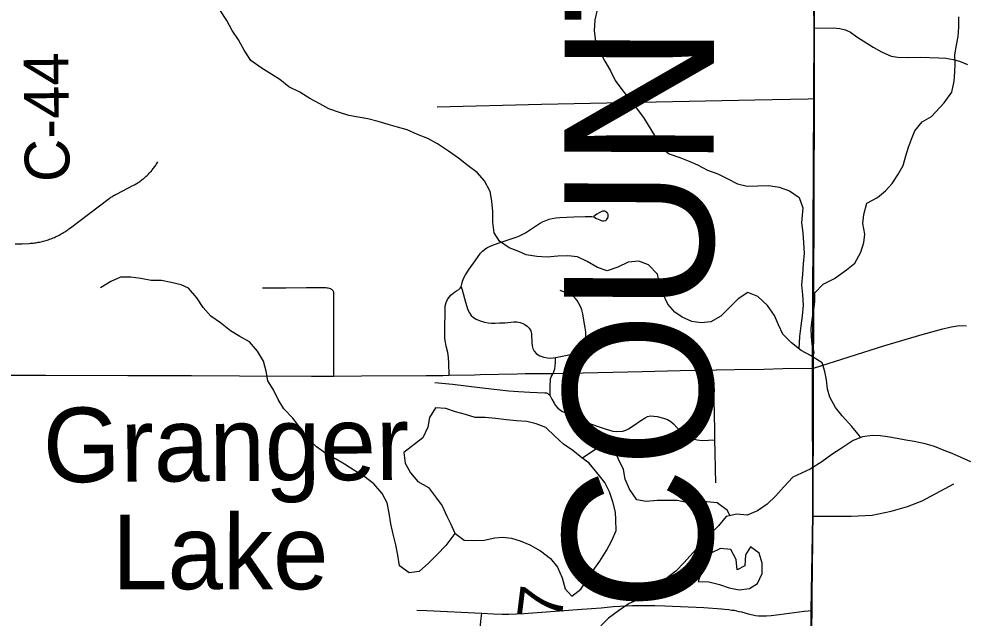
# Model space of a CAD drawing. Extents: x 0 to 34, y 0 to 22.
# Drawn here: x 6.974 to 8.175, y 15.589 to 16.35 of the extents above; entities that cross this region are included whole.
import ezdxf

# ---------------------------------------------------------------- set-up
doc = ezdxf.new("R2010")
doc.units = 0
for name, color, linetype in [('GM_X_Corporation', 7, 'Continuous'), ('GM_X_County_Road', 7, 'Continuous'), ('GM_X_County_Road_Text', 7, 'Continuous'), ('GM_X_County_Text', 7, 'Continuous'), ('GM_X_Minor_Lake', 7, 'Continuous'), ('GM_X_Minor_Lake_Text', 7, 'Continuous'), ('GM_X_Minor_River', 7, 'Continuous'), ('GM_X_Township_Road', 7, 'Continuous'), ('GM_X_Township_Road_Text', 7, 'Continuous')]:
    doc.layers.add(name, color=color, linetype=linetype)

msp = doc.modelspace()

# ---------------------------------------------------------------- linework, layer by layer
at = {"layer": 'GM_X_Corporation'}
for points in [[(2.1, 20.9), (2.1, 14.1), (7.9734, 14.1), (7.9726, 14.5453), (7.9765, 15.2637), (7.9792, 15.5481), (7.979, 15.5988), (7.9808, 15.7192), (7.9807, 15.9078), (7.9821, 16.2487), (7.9825, 16.3395), (7.9818, 16.3982), (7.9825, 16.6077), (7.9838, 16.7968), (7.9877, 17.3871), (7.9891, 17.5498), (7.991, 17.7727), (7.9901, 18.1613)], [(7.9901, 18.1613), (7.991, 17.7727), (7.9891, 17.5498), (7.9877, 17.3871), (7.9838, 16.7968), (7.9825, 16.6077), (7.9818, 16.3982), (7.9825, 16.3395), (7.9821, 16.2487), (7.9807, 15.9078), (7.9808, 15.7192), (7.979, 15.5988), (7.9792, 15.5481), (7.9765, 15.2637), (7.9726, 14.5453), (7.9734, 14.1), (8.9, 14.1), (8.9, 20.9)], [(7.9901, 18.1613), (7.991, 17.7727), (7.9891, 17.5498), (7.9877, 17.3871), (7.9838, 16.7968), (7.9825, 16.6077), (7.9818, 16.3982), (7.9825, 16.3395), (7.9821, 16.2487), (7.9807, 15.9078), (7.9808, 15.7192), (7.979, 15.5988), (7.9792, 15.5481), (7.9765, 15.2637), (7.9726, 14.5453), (8.3169, 14.5418), (8.5518, 14.5426), (8.5844, 14.5431), (8.8409, 14.5545), (8.9, 14.5547), (8.9, 19.1229)], [(7.9901, 18.1613), (7.991, 17.7727), (7.9891, 17.5498), (7.9877, 17.3871), (7.9838, 16.7968), (7.9825, 16.6077), (7.9818, 16.3982), (7.9825, 16.3395), (7.9821, 16.2487), (7.9807, 15.9078), (7.9808, 15.7192), (7.979, 15.5988), (7.9792, 15.5481), (7.9765, 15.2637), (7.9726, 14.5453), (7.0871, 14.5429), (7.0197, 14.5427), (6.4941, 14.5412), (6.1476, 14.5397), (5.4644, 14.5374), (4.5212, 14.531)]]:
    msp.add_lwpolyline(points, dxfattribs=at)
at = {"layer": 'GM_X_County_Road'}
for p, q in [((7.9818, 15.8856), (7.9817, 15.9068)), ((7.9798, 15.5778), (7.9801, 15.5987))]:
    msp.add_line(p, q, dxfattribs=at)
for points in [[(7.9831, 16.3386), (7.9832, 16.3526), (7.983, 16.3802)], [(7.983, 16.2489), (7.983, 16.3255), (7.9831, 16.3386)], [(7.9817, 15.9068), (7.9823, 15.9679), (7.9821, 15.9789), (7.9826, 16.1376), (7.9832, 16.2296), (7.983, 16.2489)], [(7.9817, 15.9068), (7.9817, 15.9068), (8.0723, 15.9353), (8.1199, 15.9494), (8.146, 15.9564), (8.1547, 15.9588), (8.1616, 15.96), (8.1676, 15.9607), (8.1758, 15.9604)], [(6.9505, 15.8976), (7.0073, 15.8977), (7.1116, 15.8973), (7.1527, 15.8972), (7.1927, 15.8971), (7.2533, 15.897), (7.345, 15.8964), (7.3733, 15.8965), (7.4084, 15.8967), (7.4904, 15.8972), (7.5113, 15.8975), (7.5196, 15.8976), (7.5516, 15.8983), (7.5587, 15.8985), (7.6057, 15.8995), (7.6158, 15.8997), (7.6427, 15.8999), (7.6514, 15.9), (7.671, 15.9004), (7.7644, 15.9026), (7.8127, 15.9036), (7.8814, 15.9048), (7.9188, 15.9052), (7.9428, 15.906), (7.9817, 15.9068)], [(7.9811, 15.7187), (7.9814, 15.7417), (7.9816, 15.7559), (7.9817, 15.8333), (7.9818, 15.8715), (7.9818, 15.8856)], [(7.9801, 15.5987), (7.9802, 15.6084), (7.9807, 15.6625), (7.9808, 15.6779), (7.981, 15.7048), (7.9811, 15.7187)]]:
    msp.add_lwpolyline(points, dxfattribs=at)
at = {"layer": 'GM_X_Minor_Lake'}
for points in [[(7.697, 15.786), (7.688, 15.7927), (7.6766, 15.8019), (7.6644, 15.8102), (7.6534, 15.8201), (7.6423, 15.8311), (7.6301, 15.836), (7.618, 15.8391), (7.605, 15.8398), (7.5921, 15.8409), (7.5784, 15.8428), (7.5654, 15.8439), (7.5525, 15.8439), (7.5403, 15.8477), (7.5274, 15.8511), (7.5152, 15.8553), (7.5023, 15.8564), (7.4947, 15.8438), (7.4924, 15.8317), (7.4863, 15.818), (7.462, 15.7997), (7.4636, 15.786), (7.4704, 15.7738), (7.4799, 15.7628), (7.4933, 15.7549)], [(7.6968, 15.7862), (7.688, 15.7927), (7.6766, 15.8019), (7.6644, 15.8102), (7.6534, 15.8201), (7.6423, 15.8311), (7.6301, 15.836), (7.618, 15.8391), (7.605, 15.8398), (7.5921, 15.8409), (7.5784, 15.8428), (7.5654, 15.8439), (7.5525, 15.8439), (7.5403, 15.8477), (7.5274, 15.8511), (7.5152, 15.8553), (7.5023, 15.8564), (7.4947, 15.8438), (7.4924, 15.8317), (7.4863, 15.818), (7.462, 15.7997), (7.4636, 15.786), (7.4704, 15.7738), (7.4799, 15.7628), (7.4933, 15.7549)], [(7.4933, 15.7549), (7.502, 15.7431), (7.5108, 15.7317), (7.5165, 15.7188), (7.5211, 15.7092), (7.5268, 15.6971), (7.5387, 15.688), (7.5508, 15.6876), (7.5638, 15.688), (7.5775, 15.6911), (7.587, 15.6918), (7.5984, 15.6907), (7.6098, 15.6873), (7.622, 15.6824), (7.6353, 15.6748), (7.6483, 15.6649), (7.657, 15.6539), (7.6631, 15.6402), (7.6666, 15.6265), (7.675, 15.617), (7.6868, 15.6258), (7.694, 15.6376), (7.7023, 15.6498), (7.7107, 15.6616), (7.719, 15.6749), (7.7259, 15.6878), (7.7315, 15.7004), (7.7308, 15.7141), (7.7304, 15.7236), (7.7273, 15.7369), (7.7231, 15.7494), (7.717, 15.7616), (7.7071, 15.7741), (7.6968, 15.7863)], [(7.4933, 15.7549), (7.502, 15.7431), (7.5108, 15.7317), (7.5165, 15.7188), (7.5211, 15.7092), (7.5268, 15.6971), (7.5387, 15.688), (7.5508, 15.6876), (7.5638, 15.688), (7.5775, 15.6911), (7.587, 15.6918), (7.5984, 15.6907), (7.6098, 15.6873), (7.622, 15.6824), (7.6353, 15.6748), (7.6483, 15.6649), (7.657, 15.6539), (7.6631, 15.6402), (7.6666, 15.6265), (7.675, 15.617), (7.6868, 15.6258), (7.694, 15.6376), (7.7023, 15.6498), (7.7107, 15.6616), (7.719, 15.6749), (7.7259, 15.6878), (7.7315, 15.7004), (7.7308, 15.7141), (7.7304, 15.7236), (7.7273, 15.7369), (7.7231, 15.7494), (7.717, 15.7616), (7.7071, 15.7741), (7.697, 15.786)], [(7.8355, 15.6359), (7.8492, 15.6351), (7.8625, 15.6317), (7.8747, 15.6275), (7.8877, 15.6253), (7.9006, 15.6268), (7.9109, 15.6333), (7.9169, 15.6459), (7.9169, 15.6588), (7.9127, 15.6717), (7.902, 15.6797), (7.8956, 15.6694), (7.8948, 15.6557)], [(7.8355, 15.6359), (7.8492, 15.6351), (7.8625, 15.6317), (7.8747, 15.6275), (7.8877, 15.6253), (7.9006, 15.6268), (7.9109, 15.6333), (7.9169, 15.6459), (7.9169, 15.6588), (7.9127, 15.6717), (7.902, 15.6797), (7.8956, 15.6694), (7.8948, 15.6557)], [(7.8948, 15.6557), (7.885, 15.6504), (7.8838, 15.6637), (7.8769, 15.6762), (7.864, 15.6777), (7.8514, 15.6716), (7.8431, 15.6591), (7.8355, 15.6359)], [(7.8948, 15.6557), (7.885, 15.6504), (7.8838, 15.6637), (7.8769, 15.6762), (7.864, 15.6777), (7.8514, 15.6716), (7.8431, 15.6591), (7.8355, 15.6356)]]:
    msp.add_lwpolyline(points, dxfattribs=at)
at = {"layer": 'GM_X_Minor_River'}
for points in [[(7.9781, 15.9225), (7.966, 15.9289), (7.9538, 15.9387), (7.9431, 15.9497), (7.9374, 15.9615), (7.9324, 15.9733), (7.9233, 15.9862), (7.9111, 15.9976), (7.8985, 16.0026), (7.8864, 15.9946), (7.8753, 15.9835), (7.8643, 15.9728), (7.8514, 15.9656), (7.8392, 15.9641), (7.8274, 15.966), (7.8152, 15.9713), (7.8057, 15.9777), (7.797, 15.988), (7.7905, 16.0013), (7.7866, 16.0142), (7.784, 16.026), (7.7725, 16.0378), (7.76, 16.0427), (7.7467, 16.0412), (7.7337, 16.0347), (7.72, 16.0301), (7.7079, 16.0346), (7.6945, 16.0422), (7.6823, 16.0479), (7.6702, 16.0494), (7.6576, 16.049), (7.6439, 16.0475), (7.6306, 16.0486), (7.6173, 16.0505), (7.6078, 16.0547), (7.5956, 16.0596), (7.5834, 16.0679), (7.5765, 16.0786), (7.575, 16.0919), (7.575, 16.1056), (7.5738, 16.1185), (7.5715, 16.1311), (7.5642, 16.1444), (7.5551, 16.155), (7.5437, 16.1637), (7.5315, 16.1732), (7.5185, 16.1823), (7.5048, 16.1914), (7.4923, 16.1983), (7.4793, 16.2032), (7.4664, 16.2093), (7.4538, 16.2127), (7.442, 16.2161), (7.4294, 16.2199), (7.4161, 16.2233), (7.4039, 16.2252), (7.3921, 16.2274), (7.3803, 16.2312), (7.367, 16.2358), (7.3552, 16.2422), (7.3426, 16.249), (7.3301, 16.257), (7.316, 16.2638), (7.3046, 16.2733), (7.2909, 16.2817), (7.2809, 16.2881), (7.268, 16.2973), (7.2592, 16.3106), (7.252, 16.3235), (7.244, 16.3356), (7.2375, 16.3482), (7.2285, 16.3618)], [(7.7074, 16.3617), (7.7044, 16.3488), (7.7036, 16.3351), (7.7052, 16.3218), (7.7105, 16.3088), (7.717, 16.2963), (7.7242, 16.2841), (7.73, 16.272), (7.7387, 16.2606), (7.7479, 16.2488), (7.7566, 16.2374), (7.7662, 16.2249), (7.7814, 16.1998), (7.7872, 16.1876), (7.7986, 16.1789), (7.8123, 16.174), (7.8249, 16.169), (7.8348, 16.1649), (7.8473, 16.158), (7.8603, 16.1535), (7.8721, 16.1474), (7.8854, 16.1406), (7.8976, 16.1379), (7.9113, 16.138), (7.925, 16.1387), (7.9383, 16.1365), (7.9512, 16.1319), (7.9638, 16.1232), (7.9684, 16.1103), (7.9673, 16.1008), (7.9665, 16.0912), (7.9681, 16.0787), (7.9692, 16.0658), (7.97, 16.0528), (7.9689, 16.0392), (7.9677, 16.0262), (7.9666, 16.0125), (7.9678, 15.9996), (7.9686, 15.9867), (7.9674, 15.973), (7.9659, 15.9604), (7.9641, 15.9467), (7.9632, 15.9311)], [(7.981, 15.9209), (7.9827, 15.9264), (7.9803, 15.9371), (7.9795, 15.9465), (7.979, 15.9572), (7.9807, 15.9713), (7.9822, 15.9811), (7.9836, 15.9907), (7.9835, 16.0024), (7.994, 16.0132), (8.0084, 16.0205), (8.0239, 16.0313), (8.0344, 16.0401), (8.0419, 16.0539), (8.0459, 16.0661), (8.047, 16.0767), (8.0446, 16.0904), (8.0456, 16.1018), (8.0497, 16.1163), (8.0629, 16.1232), (8.0734, 16.1317), (8.0817, 16.1413), (8.0888, 16.152), (8.0955, 16.1642), (8.0992, 16.1764), (8.1025, 16.1871), (8.1062, 16.1974), (8.1103, 16.208), (8.1197, 16.2195), (8.1314, 16.2261), (8.1476, 16.2434), (8.1573, 16.2571), (8.1602, 16.2712), (8.1612, 16.2826), (8.1615, 16.2936), (8.1614, 16.3043), (8.1629, 16.3145), (8.1654, 16.3279), (8.1664, 16.3397), (8.1663, 16.3526)], [(7.5268, 15.6968), (7.5151, 15.6815), (7.5044, 15.6701), (7.4934, 15.659), (7.4816, 15.6484), (7.4687, 15.6468), (7.4565, 15.6555), (7.4542, 15.6692), (7.4519, 15.6822), (7.4485, 15.6958), (7.4454, 15.7088), (7.4435, 15.7225), (7.4408, 15.7354), (7.4343, 15.7475), (7.424, 15.7597), (7.4111, 15.7696), (7.3985, 15.7772), (7.3867, 15.7848), (7.3753, 15.7916), (7.3631, 15.7984), (7.3513, 15.8068), (7.3398, 15.8174), (7.3303, 15.8307), (7.3212, 15.8432), (7.3097, 15.855), (7.3025, 15.8668), (7.2964, 15.8793), (7.2895, 15.8907), (7.2872, 15.9029), (7.2838, 15.9155), (7.2761, 15.9284), (7.2662, 15.9402), (7.254, 15.947), (7.2422, 15.9542), (7.2293, 15.9641), (7.2171, 15.9728), (7.2072, 15.9838), (7.1992, 15.996), (7.1889, 16.0081), (7.1794, 16.0123), (7.1668, 16.0153), (7.1543, 16.018), (7.1413, 16.018), (7.1284, 16.0206), (7.1154, 16.0221), (7.1025, 16.0221), (7.09, 16.0168), (7.077, 16.0088)], [(8.0412, 15.8184), (8.0402, 15.8206), (8.0306, 15.8327), (8.0183, 15.8462), (8.0099, 15.8568), (8.0025, 15.8696), (7.9998, 15.8799), (7.9982, 15.8916), (7.9962, 15.9022), (7.993, 15.9132), (7.978, 15.9227)], [(8.1816, 15.7877), (8.1691, 15.7933), (8.158, 15.7981), (8.1477, 15.8022), (8.1352, 15.807), (8.1234, 15.8107), (8.1097, 15.8133), (8.099, 15.8151), (8.088, 15.8172), (8.0758, 15.8194), (8.0663, 15.8208), (8.0565, 15.8211), (8.044, 15.8195), (8.0322, 15.8148), (8.0168, 15.8044), (8.0051, 15.7971), (7.9926, 15.7878)], [(7.8757, 15.7194), (7.8727, 15.726), (7.8597, 15.7355), (7.8464, 15.737), (7.8338, 15.737), (7.8205, 15.7362), (7.8087, 15.7385), (7.7836, 15.7385), (7.7695, 15.7373), (7.7577, 15.7396), (7.7482, 15.7529), (7.7429, 15.7658), (7.7406, 15.778), (7.7345, 15.7909), (7.7291, 15.8027), (7.7169, 15.8072), (7.7055, 15.8038), (7.6888, 15.7922)], [(7.9926, 15.7878), (7.9776, 15.7782)], [(7.9776, 15.7782), (7.9556, 15.768), (7.9442, 15.7558), (7.9339, 15.7444), (7.9229, 15.7341), (7.9107, 15.7253), (7.8978, 15.72), (7.8845, 15.7211), (7.8712, 15.7184), (7.8613, 15.7066), (7.8499, 15.6952), (7.8393, 15.6834), (7.8286, 15.672), (7.8176, 15.6598), (7.807, 15.6488), (7.7944, 15.6392), (7.7826, 15.6278), (7.7701, 15.6179), (7.7606, 15.6133), (7.748, 15.6076), (7.7344, 15.5985), (7.7218, 15.5893), (7.7119, 15.5794)]]:
    msp.add_lwpolyline(points, dxfattribs=at)
at = {"layer": 'GM_X_Township_Road'}
for points in [[(7.9831, 16.3386), (8.0068, 16.3388), (8.0151, 16.3381), (8.0225, 16.3365), (8.029, 16.3335), (8.0367, 16.3276), (8.0575, 16.3142), (8.0681, 16.3082), (8.0806, 16.303), (8.0889, 16.3015), (8.102, 16.301), (8.1172, 16.3015), (8.1407, 16.3008), (8.1499, 16.3001), (8.1589, 16.2985), (8.1672, 16.2964), (8.1771, 16.2923)], [(7.5041, 16.2386), (7.6365, 16.2419), (7.6988, 16.2432), (7.9073, 16.2474), (7.9751, 16.2487), (7.983, 16.2489)], [(6.9689, 16.0645), (6.9775, 16.0647), (6.9867, 16.0651), (6.9883, 16.0652), (6.99, 16.0653), (6.9916, 16.0655), (6.9932, 16.0657), (6.9948, 16.0659), (6.9965, 16.0662), (6.9981, 16.0665), (6.9997, 16.0668), (7.0013, 16.0671), (7.0029, 16.0675), (7.0045, 16.0679), (7.0061, 16.0683), (7.0077, 16.0688), (7.0092, 16.0692), (7.0108, 16.0698), (7.0124, 16.0703), (7.0139, 16.0709), (7.0154, 16.0715), (7.017, 16.0721), (7.0185, 16.0727), (7.02, 16.0734), (7.0215, 16.0741), (7.0229, 16.0748), (7.0244, 16.0756), (7.0259, 16.0764), (7.0273, 16.0772), (7.0287, 16.078), (7.0301, 16.0788), (7.0316, 16.0797), (7.0329, 16.0806), (7.0343, 16.0815), (7.0357, 16.0825), (7.037, 16.0834), (7.0388, 16.0848), (7.0863, 16.1208), (7.0881, 16.1221), (7.0892, 16.1228), (7.0903, 16.1236), (7.0914, 16.1243), (7.0925, 16.125), (7.0937, 16.1257), (7.0948, 16.1263), (7.096, 16.127), (7.0972, 16.1276), (7.1189, 16.1389), (7.1201, 16.1396), (7.1213, 16.1402), (7.1224, 16.1409), (7.1235, 16.1416), (7.1247, 16.1423), (7.1258, 16.143), (7.1269, 16.1437), (7.128, 16.1445), (7.129, 16.1453), (7.1301, 16.1461), (7.1311, 16.1469), (7.1321, 16.1477), (7.1332, 16.1486), (7.1342, 16.1495), (7.1351, 16.1503), (7.1361, 16.1512), (7.1371, 16.1522), (7.138, 16.1531), (7.1389, 16.1541), (7.1398, 16.155), (7.1407, 16.156), (7.1416, 16.157), (7.1424, 16.158), (7.1432, 16.1591), (7.144, 16.1601), (7.1448, 16.1612), (7.1456, 16.1623), (7.1464, 16.1633), (7.1471, 16.1644), (7.1478, 16.1656), (7.1485, 16.1667), (7.1497, 16.1687)], [(7.5196, 15.8976), (7.5192, 15.9129), (7.5188, 15.9202), (7.5178, 15.9264), (7.5157, 15.9347), (7.5147, 15.9397), (7.5141, 15.9442), (7.514, 15.9503), (7.5146, 15.9853), (7.5158, 15.99), (7.5176, 15.9937), (7.5197, 15.9969), (7.5221, 15.9996), (7.5261, 16.0031), (7.5287, 16.0049), (7.5316, 16.0066), (7.5335, 16.0081), (7.5347, 16.0099), (7.5354, 16.0131), (7.5364, 16.0171), (7.538, 16.0215), (7.5402, 16.0253), (7.5451, 16.0325), (7.5524, 16.043), (7.5593, 16.0528), (7.5617, 16.0551), (7.5643, 16.0573), (7.5675, 16.0594), (7.5709, 16.0613), (7.5757, 16.0633), (7.5841, 16.0664), (7.5981, 16.0707), (7.6045, 16.073), (7.6088, 16.0747), (7.6123, 16.0764), (7.6162, 16.0786), (7.6302, 16.0879), (7.6342, 16.0904), (7.6381, 16.0923), (7.6422, 16.0942), (7.6466, 16.0958), (7.6503, 16.0967), (7.6548, 16.0975), (7.66, 16.0981), (7.6776, 16.0989), (7.6921, 16.0992), (7.7005, 16.0991), (7.7025, 16.0987), (7.7044, 16.098), (7.7065, 16.0969), (7.7084, 16.0959), (7.7108, 16.0948), (7.7126, 16.0942), (7.7141, 16.0939), (7.7157, 16.0938), (7.7183, 16.0942), (7.7192, 16.0951), (7.7202, 16.0963), (7.721, 16.0975), (7.7214, 16.0989), (7.7211, 16.102), (7.7205, 16.103), (7.7198, 16.1042), (7.7184, 16.1053), (7.7169, 16.1059), (7.7156, 16.106), (7.7141, 16.1059), (7.7123, 16.1053), (7.7098, 16.1038), (7.7069, 16.1021), (7.7031, 16.0993)], [(7.5347, 16.0099), (7.536, 16.006), (7.5402, 15.9906), (7.5434, 15.9805), (7.5452, 15.9768), (7.5476, 15.9735), (7.5503, 15.9708), (7.5538, 15.9687), (7.5587, 15.9669), (7.5645, 15.9651), (7.5691, 15.9642), (7.5729, 15.9639), (7.5779, 15.9638), (7.5832, 15.964), (7.59, 15.9644), (7.6016, 15.9654), (7.6055, 15.9653), (7.6096, 15.9647), (7.613, 15.9635), (7.6155, 15.962), (7.6185, 15.96), (7.621, 15.9574), (7.623, 15.9541), (7.624, 15.9504), (7.6243, 15.939), (7.6247, 15.935), (7.6257, 15.9318), (7.6272, 15.9284), (7.6305, 15.925), (7.6347, 15.9224), (7.6395, 15.9208), (7.6442, 15.9198), (7.6484, 15.9194), (7.6515, 15.9196), (7.6543, 15.92), (7.6587, 15.9209), (7.6734, 15.9241), (7.6798, 15.926), (7.6847, 15.9279), (7.6879, 15.9298), (7.6898, 15.932), (7.6914, 15.9346), (7.6922, 15.9383), (7.6929, 15.9424), (7.6931, 15.9473), (7.6928, 15.9529), (7.6923, 15.9579), (7.6905, 15.9677), (7.689, 15.9758), (7.6877, 15.9807), (7.6861, 15.9849), (7.684, 15.9888), (7.682, 15.9925), (7.6797, 15.9952), (7.6775, 15.9972), (7.6746, 15.9993), (7.6714, 16.0011), (7.6671, 16.0028), (7.6604, 16.0053)], [(7.3733, 15.8965), (7.3731, 16.0027), (7.3729, 16.0038), (7.3721, 16.005), (7.3712, 16.0059), (7.3704, 16.0065), (7.3693, 16.0072), (7.3677, 16.0077), (7.3659, 16.0081), (7.3645, 16.0083), (7.3629, 16.0085), (7.3609, 16.0086), (7.3386, 16.0085), (7.3121, 16.0084), (7.2828, 16.0083)], [(7.6514, 15.9), (7.6529, 15.9031), (7.6537, 15.9056), (7.6542, 15.9091), (7.6544, 15.9141), (7.6543, 15.92)], [(7.6478, 15.8714), (7.6475, 15.8798), (7.6476, 15.8854), (7.6479, 15.8903), (7.6483, 15.893), (7.649, 15.8956), (7.6514, 15.9)], [(7.5014, 15.8883), (7.5237, 15.8861), (7.562, 15.8818), (7.5954, 15.878), (7.6076, 15.8769), (7.6218, 15.8761), (7.641, 15.8753), (7.643, 15.8751), (7.6447, 15.8743), (7.646, 15.8733), (7.6478, 15.8714), (7.65, 15.8673), (7.6527, 15.8623), (7.6546, 15.8591), (7.6572, 15.8559), (7.6626, 15.8522), (7.6678, 15.8495), (7.6816, 15.8431), (7.6955, 15.8373), (7.7084, 15.8326), (7.7186, 15.8292), (7.7274, 15.8268), (7.732, 15.8263), (7.7401, 15.8268), (7.7435, 15.8278), (7.7471, 15.8297), (7.7528, 15.8332), (7.7626, 15.8403), (7.7681, 15.8437), (7.7714, 15.8452), (7.7748, 15.846), (7.7835, 15.8454), (7.7914, 15.8433), (7.7965, 15.8415), (7.8008, 15.8391), (7.8042, 15.836), (7.8085, 15.8313), (7.8129, 15.8263), (7.8168, 15.8227), (7.8209, 15.82), (7.8273, 15.8175), (7.8344, 15.8156), (7.8407, 15.8149), (7.8568, 15.8158)], [(7.8577, 15.7612), (7.8575, 15.7788), (7.8572, 15.8), (7.8568, 15.8158), (7.8567, 15.8284), (7.8559, 15.8663), (7.8558, 15.8849)], [(7.9811, 15.7187), (8.0296, 15.7185), (8.0564, 15.72), (8.0806, 15.725), (8.1013, 15.7309), (8.1196, 15.738), (8.16, 15.7598)], [(7.4786, 15.5992), (7.4911, 15.5988), (7.5609, 15.5953), (7.5757, 15.5945), (7.5867, 15.5942), (7.5952, 15.5941), (7.605, 15.5947), (7.6142, 15.5952), (7.688, 15.6006), (7.7126, 15.6024), (7.7275, 15.6038), (7.7363, 15.6044), (7.7443, 15.6049), (7.7521, 15.6051), (7.7684, 15.6052), (7.7805, 15.6052), (7.793, 15.6049), (7.8428, 15.6025), (7.8649, 15.6011), (7.8689, 15.6007), (7.8743, 15.6), (7.878, 15.5995), (7.881, 15.5991), (7.884, 15.5986), (7.8872, 15.5978), (7.8905, 15.597), (7.8988, 15.5948), (7.9049, 15.5932), (7.9083, 15.5925), (7.9121, 15.5921), (7.9171, 15.5919), (7.9224, 15.592), (7.928, 15.5924), (7.9381, 15.5937), (7.9699, 15.5979), (7.9801, 15.5987)], [(7.5554, 15.4617), (7.5556, 15.4896), (7.5559, 15.5034), (7.5561, 15.5163), (7.5563, 15.53), (7.5565, 15.5415), (7.5571, 15.5513), (7.5576, 15.5599), (7.5583, 15.5682), (7.559, 15.5745), (7.5599, 15.5853), (7.5609, 15.5953)]]:
    msp.add_lwpolyline(points, dxfattribs=at)

# ---------------------------------------------------------------- texts
at = {"layer": 'GM_X_County_Road_Text'}
msp.add_text('C-44', height=0.05682, rotation=90.6823, dxfattribs=at).set_placement((7.038, 16.1433))
at = {"layer": 'GM_X_County_Text'}
msp.add_text('MEDINA COUNTY', height=0.189394, rotation=89.8023, dxfattribs=at).set_placement((7.8494, 14.542))
at = {"layer": 'GM_X_Minor_Lake_Text'}
for s, rotation, p in [('Granger', 0.4207, (7.0043, 15.7615)), ('Lake', 359.982, (7.0917, 15.6259))]:
    msp.add_text(s, height=0.09474, rotation=rotation, dxfattribs=at).set_placement(p)
at = {"layer": 'GM_X_Township_Road_Text'}
msp.add_text('7', height=0.0568, rotation=82.8937, dxfattribs=at).set_placement((7.6617, 15.584))

doc.saveas('drawing.dxf')
